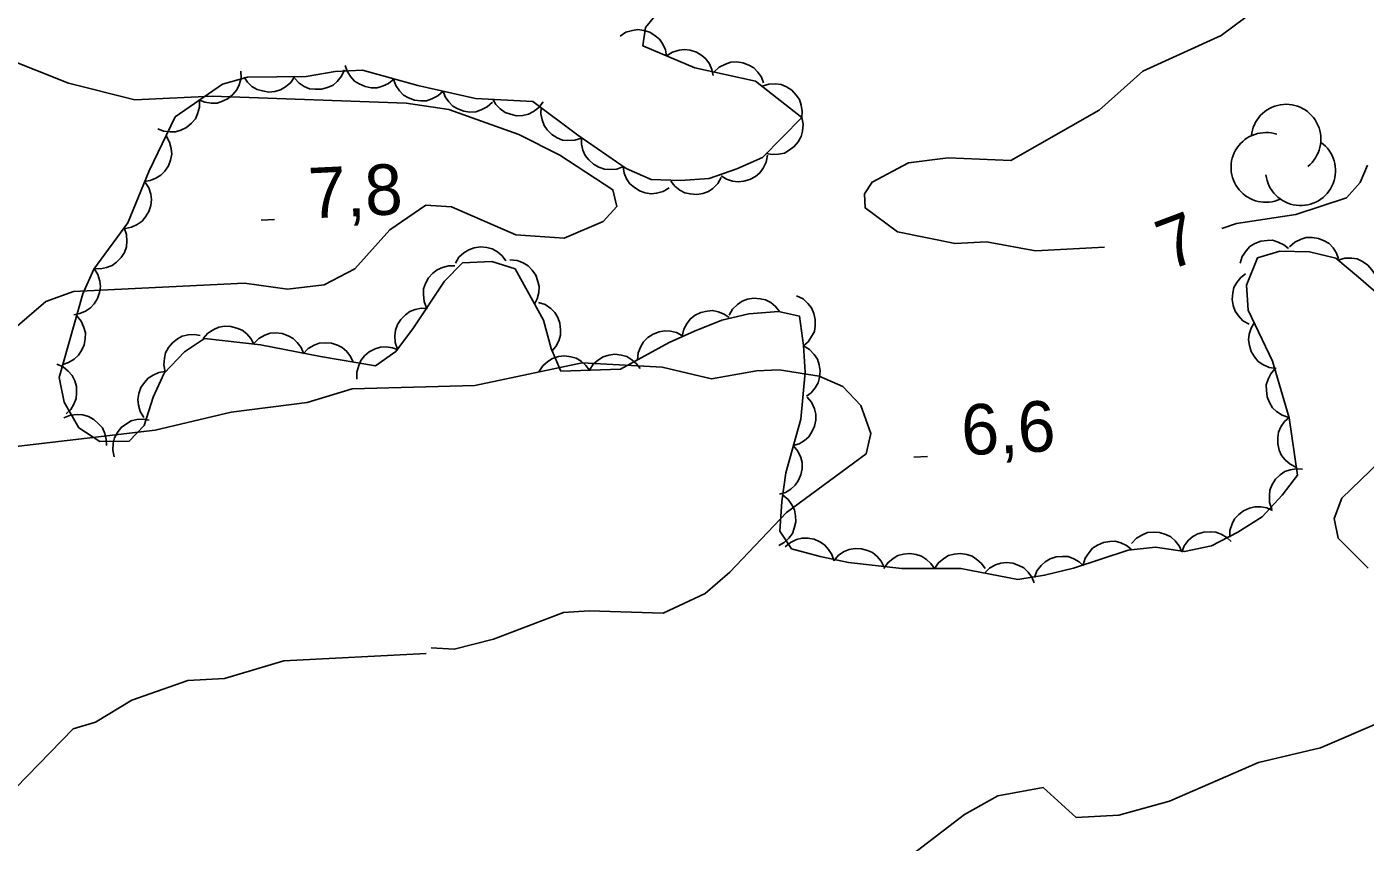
# Model space of a CAD drawing. Extents: x 336540 to 340074, y 5572036 to 5573747.
# Drawn here: x 337234.8 to 337314.2, y 5572821.1 to 5572869.5 of the extents above; entities that cross this region are included whole.
import ezdxf

# ---------------------------------------------------------------- set-up
doc = ezdxf.new("R2010")
doc.units = 0
for name, color, linetype in [('Niveau 2', 7, 'Continuous'), ('Niveau 3', 7, 'Continuous'), ('Niveau 44', 7, 'Continuous')]:
    doc.layers.add(name, color=color, linetype=linetype)

msp = doc.modelspace()

# ---------------------------------------------------------------- linework, layer by layer
at = {"layer": 'Niveau 2'}
for points in [[(337298.77, 5572856.38), (337294.68, 5572856.17), (337291.76, 5572856.69), (337289.9, 5572856.59), (337286.49, 5572857.28), (337284.56, 5572858.71), (337284.52, 5572859.55), (337284.98, 5572860.24), (337287.13, 5572861.38), (337289.49, 5572861.68), (337293.2, 5572861.53), (337298.46, 5572864.51), (337301.05, 5572866.83), (337305.69, 5572868.94), (337307.16, 5572870.03), (337310.32, 5572871.05), (337315.02, 5572871.79)], [(337229.71, 5572869.12), (337237.29, 5572866.11), (337241.23, 5572865.13), (337245.81, 5572865.35), (337257.33, 5572864.93), (337259.87, 5572864.55), (337264.02, 5572863.07), (337266.45, 5572861.84), (337269.6, 5572859.79), (337269.82, 5572858.8), (337269.02, 5572857.91), (337266.7, 5572856.92), (337263.83, 5572857.11), (337260.01, 5572858.78), (337258.49, 5572858.88), (337256.35, 5572857.41), (337254.28, 5572855.1), (337252.47, 5572854.15), (337250.28, 5572853.89), (337247.74, 5572854.25), (337237.59, 5572853.74), (337235.95, 5572853.15), (337233.82, 5572851.34)], [(337314.38, 5572861.25), (337313.93, 5572860.22), (337313.12, 5572859.31), (337310.13, 5572858.31), (337306.61, 5572857.79), (337305.73, 5572857.48)], [(337231.98, 5572844.29), (337242.43, 5572845.51), (337246.94, 5572846.58), (337251.46, 5572847.15), (337254.13, 5572847.97), (337261.4, 5572848.17), (337267.77, 5572849.52), (337272.51, 5572849.26), (337275.44, 5572848.57), (337278.12, 5572849.03), (337279.46, 5572849.09), (337281.84, 5572848.72), (337283.25, 5572848.11), (337284.3, 5572846.98), (337284.91, 5572845.32), (337284.63, 5572844.12), (337279.89, 5572840.63), (337276.53, 5572837.08), (337275.07, 5572835.82), (337272.58, 5572834.66), (337268.18, 5572834.79), (337266.66, 5572834.7), (337262.51, 5572833.12), (337260.18, 5572832.51), (337258.81, 5572832.59)], [(337315.11, 5572843.66), (337312.86, 5572841.49), (337312.4, 5572840.28), (337312.63, 5572839.11), (337314.42, 5572837.33)], [(337229.38, 5572819.38), (337237.57, 5572827.79), (337238.9, 5572828.19), (337241.04, 5572829.5), (337244.37, 5572830.66), (337246.55, 5572830.78), (337250.07, 5572831.83), (337258.51, 5572832.26)], [(337315.22, 5572828.22), (337311.58, 5572826.67), (337307.91, 5572825.8), (337302.62, 5572823.49), (337299.61, 5572822.66), (337297.08, 5572822.53), (337295.12, 5572824.3), (337292.44, 5572823.82), (337290.47, 5572822.71), (337286.4, 5572819.61)]]:
    msp.add_lwpolyline(points, dxfattribs=at)
at = {"layer": 'Niveau 3'}
for p, q in [((337248.72, 5572857.98), (337249.52, 5572858.02)), ((337287.46, 5572843.92), (337288.26, 5572843.96))]:
    msp.add_line(p, q, dxfattribs=at)
at = {"layer": 'Niveau 44'}
for points in [[(337272.63, 5572870.77), (337271.53, 5572869.42), (337271.37, 5572868.33), (337274.45, 5572867.03), (337278.06, 5572866.24), (337280.8, 5572864.08), (337278.48, 5572861.71), (337276.96, 5572861.03), (337275.3, 5572860.46), (337273.61, 5572860.33), (337271.86, 5572860.39), (337270.39, 5572861.05), (337267.51, 5572863.02), (337264.85, 5572865.03), (337261.45, 5572865.21), (337258.02, 5572865.98), (337254.74, 5572866.88), (337253.11, 5572866.81), (337251.39, 5572866.5), (337247.91, 5572866.47), (337246.42, 5572866.05), (337243.62, 5572864.11), (337242.08, 5572860.9), (337240.82, 5572857.83), (337238.8, 5572855.07), (337238.15, 5572853.6), (337236.74, 5572848.65), (337237.03, 5572847.17), (337237.91, 5572845.66), (337239.16, 5572844.85), (337240.9, 5572844.87), (337241.78, 5572845.8), (337242.32, 5572847.48), (337242.96, 5572848.9), (337244.17, 5572850.16), (337245.37, 5572850.95), (337248.69, 5572850.59), (337252.25, 5572849.88), (337255.51, 5572849.33), (337256.72, 5572850.19), (337257.76, 5572851.6), (337259.6, 5572854.36), (337260.67, 5572855.44), (337262.42, 5572855.53), (337263.79, 5572855.09), (337265.47, 5572852.05), (337265.94, 5572850.36), (337266.51, 5572849.02), (337270.05, 5572849.13), (337272.94, 5572850.73), (337274.44, 5572851.39), (337276.07, 5572852.04), (337277.67, 5572852.43), (337279.42, 5572852.57), (337280.67, 5572852.28), (337280.91, 5572850.55), (337281, 5572848.96), (337280.75, 5572846.18), (337279.85, 5572842.98), (337279.63, 5572841.28), (337279.51, 5572839.53), (337280.2, 5572838.48), (337281.89, 5572838.01), (337283.57, 5572837.67), (337286.74, 5572837.3), (337290.25, 5572837.3), (337293.63, 5572836.65), (337295.21, 5572836.91), (337296.92, 5572837.32), (337300.17, 5572838.39)], [(337270.02, 5572868.9), (337270.37, 5572869.13), (337270.76, 5572869.24), (337271.08, 5572869.29), (337271.43, 5572869.24), (337271.78, 5572869.13), (337272.11, 5572868.92), (337272.36, 5572868.72), (337272.56, 5572868.43), (337272.71, 5572868.09), (337272.78, 5572867.74)], [(337272.78, 5572867.74), (337273.13, 5572867.96), (337273.52, 5572868.08), (337273.85, 5572868.12), (337274.19, 5572868.08), (337274.55, 5572867.96), (337274.87, 5572867.76), (337275.12, 5572867.55), (337275.32, 5572867.26), (337275.47, 5572866.92), (337275.54, 5572866.57)], [(337256.61, 5572866.37), (337256.29, 5572866.1), (337255.92, 5572865.93), (337255.6, 5572865.84), (337255.25, 5572865.84), (337254.89, 5572865.91), (337254.54, 5572866.07), (337254.26, 5572866.24), (337254.03, 5572866.51), (337253.83, 5572866.82), (337253.71, 5572867.16)], [(337275.61, 5572866.78), (337275.91, 5572867.06), (337276.28, 5572867.25), (337276.59, 5572867.35), (337276.94, 5572867.37), (337277.31, 5572867.32), (337277.66, 5572867.18), (337277.95, 5572867.03), (337278.19, 5572866.77), (337278.41, 5572866.47), (337278.54, 5572866.14)], [(337247.52, 5572866.82), (337247.53, 5572866.4), (337247.42, 5572866.01), (337247.28, 5572865.71), (337247.05, 5572865.44), (337246.77, 5572865.2), (337246.42, 5572865.04), (337246.11, 5572864.93), (337245.76, 5572864.92), (337245.39, 5572864.98), (337245.06, 5572865.11)], [(337250.71, 5572866.49), (337250.48, 5572866.15), (337250.16, 5572865.89), (337249.88, 5572865.71), (337249.54, 5572865.62), (337249.17, 5572865.58), (337248.8, 5572865.65), (337248.48, 5572865.73), (337248.18, 5572865.92), (337247.91, 5572866.17), (337247.71, 5572866.47)], [(337253.67, 5572866.91), (337253.5, 5572866.53), (337253.23, 5572866.22), (337252.99, 5572866), (337252.67, 5572865.85), (337252.31, 5572865.76), (337251.93, 5572865.75), (337251.6, 5572865.78), (337251.28, 5572865.92), (337250.97, 5572866.12), (337250.72, 5572866.38)], [(337259.52, 5572865.64), (337259.21, 5572865.36), (337258.85, 5572865.18), (337258.54, 5572865.07), (337258.19, 5572865.06), (337257.82, 5572865.11), (337257.46, 5572865.25), (337257.18, 5572865.41), (337256.93, 5572865.66), (337256.72, 5572865.97), (337256.59, 5572866.3)], [(337262.45, 5572864.99), (337262.14, 5572864.7), (337261.78, 5572864.52), (337261.46, 5572864.41), (337261.11, 5572864.4), (337260.75, 5572864.45), (337260.39, 5572864.59), (337260.1, 5572864.75), (337259.86, 5572865), (337259.65, 5572865.31), (337259.52, 5572865.64)], [(337278.45, 5572865.94), (337278.84, 5572866.06), (337279.25, 5572866.07), (337279.58, 5572866.03), (337279.9, 5572865.89), (337280.21, 5572865.69), (337280.47, 5572865.4), (337280.66, 5572865.14), (337280.77, 5572864.8), (337280.83, 5572864.44), (337280.8, 5572864.08)], [(337245.06, 5572865.11), (337245.06, 5572864.69), (337244.95, 5572864.3), (337244.82, 5572864), (337244.59, 5572863.73), (337244.3, 5572863.49), (337243.96, 5572863.33), (337243.65, 5572863.22), (337243.3, 5572863.22), (337242.93, 5572863.27), (337242.59, 5572863.4)], [(337265.46, 5572865), (337265.21, 5572864.66), (337264.88, 5572864.43), (337264.59, 5572864.27), (337264.25, 5572864.2), (337263.88, 5572864.18), (337263.51, 5572864.27), (337263.2, 5572864.37), (337262.91, 5572864.58), (337262.65, 5572864.85), (337262.47, 5572865.16)], [(337267.73, 5572862.85), (337267.34, 5572862.72), (337266.93, 5572862.7), (337266.6, 5572862.73), (337266.28, 5572862.87), (337265.97, 5572863.06), (337265.7, 5572863.34), (337265.51, 5572863.6), (337265.39, 5572863.93), (337265.32, 5572864.3), (337265.34, 5572864.66)], [(337280.8, 5572864.08), (337280.88, 5572863.67), (337280.84, 5572863.26), (337280.77, 5572862.94), (337280.6, 5572862.64), (337280.36, 5572862.35), (337280.05, 5572862.13), (337279.77, 5572861.96), (337279.42, 5572861.89), (337279.05, 5572861.87), (337278.7, 5572861.93)], [(337243.08, 5572862.98), (337243.29, 5572862.62), (337243.38, 5572862.23), (337243.42, 5572861.9), (337243.35, 5572861.55), (337243.22, 5572861.21), (337243, 5572860.89), (337242.78, 5572860.65), (337242.48, 5572860.47), (337242.14, 5572860.33), (337241.78, 5572860.28)], [(337270.22, 5572861.17), (337269.83, 5572861.01), (337269.42, 5572860.98), (337269.09, 5572861), (337268.76, 5572861.12), (337268.44, 5572861.3), (337268.17, 5572861.56), (337267.96, 5572861.81), (337267.82, 5572862.14), (337267.74, 5572862.5), (337267.74, 5572862.86)], [(337278.77, 5572861.84), (337278.69, 5572861.43), (337278.51, 5572861.06), (337278.32, 5572860.79), (337278.05, 5572860.57), (337277.73, 5572860.39), (337277.36, 5572860.3), (337277.03, 5572860.25), (337276.69, 5572860.3), (337276.33, 5572860.42), (337276.03, 5572860.61)], [(337272.94, 5572859.91), (337272.58, 5572859.69), (337272.19, 5572859.58), (337271.86, 5572859.54), (337271.51, 5572859.6), (337271.17, 5572859.72), (337270.85, 5572859.93), (337270.6, 5572860.14), (337270.41, 5572860.44), (337270.26, 5572860.78), (337270.2, 5572861.14)], [(337241.82, 5572860.26), (337242.05, 5572859.91), (337242.17, 5572859.53), (337242.22, 5572859.2), (337242.17, 5572858.85), (337242.06, 5572858.5), (337241.86, 5572858.17), (337241.66, 5572857.92), (337241.37, 5572857.72), (337241.03, 5572857.56), (337240.68, 5572857.49)], [(337276.03, 5572860.52), (337275.83, 5572860.15), (337275.53, 5572859.87), (337275.26, 5572859.68), (337274.93, 5572859.57), (337274.57, 5572859.5), (337274.18, 5572859.54), (337273.86, 5572859.6), (337273.56, 5572859.77), (337273.27, 5572860), (337273.04, 5572860.29)], [(337240.6, 5572857.53), (337240.74, 5572857.14), (337240.76, 5572856.73), (337240.73, 5572856.4), (337240.61, 5572856.07), (337240.41, 5572855.76), (337240.14, 5572855.49), (337239.88, 5572855.29), (337239.55, 5572855.17), (337239.19, 5572855.1), (337238.83, 5572855.11)], [(337306.82, 5572855.43), (337306.94, 5572855.83), (337307.17, 5572856.17), (337307.39, 5572856.41), (337307.69, 5572856.6), (337308.04, 5572856.73), (337308.42, 5572856.78), (337308.74, 5572856.79), (337309.08, 5572856.68), (337309.41, 5572856.52), (337309.69, 5572856.29)], [(337309.75, 5572856.4), (337310.06, 5572856.68), (337310.43, 5572856.85), (337310.74, 5572856.95), (337311.1, 5572856.96), (337311.46, 5572856.9), (337311.81, 5572856.75), (337312.1, 5572856.59), (337312.33, 5572856.33), (337312.54, 5572856.02), (337312.66, 5572855.68)], [(337260.25, 5572855.42), (337260.46, 5572855.78), (337260.76, 5572856.05), (337261.04, 5572856.23), (337261.37, 5572856.34), (337261.74, 5572856.39), (337262.12, 5572856.35), (337262.44, 5572856.28), (337262.74, 5572856.1), (337263.02, 5572855.86), (337263.24, 5572855.57)], [(337300.17, 5572838.39), (337301.79, 5572838.58), (337303.52, 5572838.31), (337305.12, 5572838.65), (337306.68, 5572839.46), (337308.13, 5572840.37), (337309.32, 5572841.65), (337310.23, 5572842.84), (337309.72, 5572846.25), (337308.74, 5572849.61), (337307.29, 5572852.63), (337307.19, 5572854.12), (337307.84, 5572855.74), (337309.18, 5572856.14), (337310.93, 5572856.11), (337312.5, 5572855.72), (337313.85, 5572854.6), (337315.03, 5572853.57)], [(337258.54, 5572852.78), (337258.39, 5572853.16), (337258.35, 5572853.57), (337258.36, 5572853.9), (337258.47, 5572854.23), (337258.65, 5572854.55), (337258.92, 5572854.83), (337259.16, 5572855.04), (337259.49, 5572855.18), (337259.85, 5572855.27), (337260.21, 5572855.27)], [(337263.49, 5572855.63), (337263.91, 5572855.59), (337264.28, 5572855.44), (337264.57, 5572855.28), (337264.81, 5572855.02), (337265.02, 5572854.71), (337265.15, 5572854.35), (337265.22, 5572854.04), (337265.2, 5572853.68), (337265.11, 5572853.32), (337264.94, 5572853)], [(337312.63, 5572855.61), (337313.03, 5572855.73), (337313.44, 5572855.73), (337313.76, 5572855.68), (337314.08, 5572855.53), (337314.39, 5572855.32), (337314.64, 5572855.03), (337314.82, 5572854.76), (337314.92, 5572854.42), (337314.97, 5572854.06), (337314.94, 5572853.7)], [(337238.82, 5572855.12), (337239.04, 5572854.76), (337239.15, 5572854.37), (337239.19, 5572854.04), (337239.14, 5572853.69), (337239.02, 5572853.34), (337238.81, 5572853.02), (337238.6, 5572852.77), (337238.3, 5572852.58), (337237.96, 5572852.44), (337237.61, 5572852.37)], [(337307.35, 5572851.8), (337306.98, 5572852.01), (337306.71, 5572852.31), (337306.52, 5572852.58), (337306.4, 5572852.92), (337306.35, 5572853.28), (337306.39, 5572853.66), (337306.45, 5572853.98), (337306.63, 5572854.29), (337306.86, 5572854.58), (337307.14, 5572854.8)], [(337256.82, 5572850.32), (337256.68, 5572850.72), (337256.66, 5572851.12), (337256.69, 5572851.45), (337256.82, 5572851.78), (337257.01, 5572852.09), (337257.29, 5572852.36), (337257.54, 5572852.56), (337257.87, 5572852.68), (337258.24, 5572852.75), (337258.6, 5572852.74)], [(337265.18, 5572853.1), (337265.57, 5572852.97), (337265.91, 5572852.73), (337266.15, 5572852.51), (337266.32, 5572852.2), (337266.45, 5572851.86), (337266.49, 5572851.47), (337266.49, 5572851.15), (337266.38, 5572850.81), (337266.21, 5572850.48), (337265.98, 5572850.21)], [(337276.49, 5572852.34), (337276.69, 5572852.7), (337276.99, 5572852.98), (337277.26, 5572853.17), (337277.59, 5572853.29), (337277.95, 5572853.35), (337278.33, 5572853.32), (337278.65, 5572853.26), (337278.96, 5572853.09), (337279.25, 5572852.86), (337279.48, 5572852.57)], [(337280.5, 5572853.49), (337280.88, 5572853.31), (337281.17, 5572853.03), (337281.38, 5572852.77), (337281.52, 5572852.45), (337281.6, 5572852.09), (337281.59, 5572851.71), (337281.55, 5572851.38), (337281.39, 5572851.07), (337281.18, 5572850.76), (337280.91, 5572850.52)], [(337237.78, 5572852.31), (337238.05, 5572851.99), (337238.21, 5572851.61), (337238.3, 5572851.3), (337238.29, 5572850.94), (337238.22, 5572850.58), (337238.06, 5572850.24), (337237.89, 5572849.96), (337237.62, 5572849.73), (337237.3, 5572849.54), (337236.96, 5572849.42)], [(337273.71, 5572851.1), (337273.8, 5572851.51), (337274, 5572851.86), (337274.2, 5572852.13), (337274.48, 5572852.34), (337274.81, 5572852.5), (337275.19, 5572852.58), (337275.51, 5572852.62), (337275.85, 5572852.55), (337276.2, 5572852.41), (337276.5, 5572852.21)], [(337243.03, 5572848.98), (337242.95, 5572849.39), (337242.98, 5572849.79), (337243.05, 5572850.11), (337243.22, 5572850.42), (337243.46, 5572850.71), (337243.76, 5572850.94), (337244.04, 5572851.1), (337244.39, 5572851.18), (337244.76, 5572851.2), (337245.11, 5572851.14)], [(337245.29, 5572850.96), (337245.56, 5572851.28), (337245.91, 5572851.5), (337246.21, 5572851.64), (337246.55, 5572851.69), (337246.92, 5572851.68), (337247.29, 5572851.58), (337247.59, 5572851.46), (337247.87, 5572851.23), (337248.11, 5572850.95), (337248.28, 5572850.63)], [(337248.28, 5572850.67), (337248.58, 5572850.96), (337248.94, 5572851.15), (337249.25, 5572851.27), (337249.6, 5572851.29), (337249.97, 5572851.25), (337250.33, 5572851.11), (337250.62, 5572850.96), (337250.87, 5572850.72), (337251.09, 5572850.42), (337251.23, 5572850.08)], [(337271.06, 5572849.69), (337271.1, 5572850.11), (337271.25, 5572850.48), (337271.42, 5572850.77), (337271.67, 5572851.01), (337271.98, 5572851.22), (337272.34, 5572851.35), (337272.66, 5572851.42), (337273.01, 5572851.4), (337273.37, 5572851.31), (337273.69, 5572851.14)], [(337308.95, 5572849.18), (337308.53, 5572849.24), (337308.17, 5572849.41), (337307.89, 5572849.59), (337307.66, 5572849.86), (337307.47, 5572850.18), (337307.37, 5572850.55), (337307.31, 5572850.87), (337307.36, 5572851.22), (337307.47, 5572851.57), (337307.65, 5572851.88)], [(337251.22, 5572850.05), (337251.51, 5572850.36), (337251.86, 5572850.56), (337252.17, 5572850.68), (337252.52, 5572850.71), (337252.89, 5572850.68), (337253.25, 5572850.56), (337253.54, 5572850.42), (337253.8, 5572850.18), (337254.03, 5572849.88), (337254.18, 5572849.55)], [(337254.41, 5572848.55), (337254.4, 5572848.96), (337254.51, 5572849.36), (337254.64, 5572849.66), (337254.86, 5572849.93), (337255.14, 5572850.17), (337255.49, 5572850.34), (337255.8, 5572850.45), (337256.15, 5572850.46), (337256.52, 5572850.41), (337256.85, 5572850.29)], [(337280.91, 5572850.52), (337281.27, 5572850.31), (337281.54, 5572850.01), (337281.73, 5572849.73), (337281.84, 5572849.4), (337281.89, 5572849.03), (337281.85, 5572848.65), (337281.78, 5572848.33), (337281.6, 5572848.03), (337281.37, 5572847.74), (337281.08, 5572847.53)], [(337265.21, 5572848.98), (337265.43, 5572849.33), (337265.74, 5572849.6), (337266.02, 5572849.78), (337266.36, 5572849.88), (337266.72, 5572849.92), (337267.1, 5572849.87), (337267.42, 5572849.79), (337267.72, 5572849.61), (337268, 5572849.36), (337268.21, 5572849.07)], [(337268.21, 5572849.07), (337268.43, 5572849.43), (337268.74, 5572849.69), (337269.02, 5572849.87), (337269.35, 5572849.97), (337269.72, 5572850.02), (337270.1, 5572849.96), (337270.42, 5572849.89), (337270.72, 5572849.7), (337271, 5572849.46), (337271.21, 5572849.17)], [(337236.59, 5572849.44), (337236.97, 5572849.28), (337237.28, 5572849.01), (337237.5, 5572848.77), (337237.66, 5572848.45), (337237.76, 5572848.1), (337237.77, 5572847.72), (337237.74, 5572847.39), (337237.61, 5572847.07), (337237.42, 5572846.75), (337237.16, 5572846.49)], [(337241.77, 5572846.26), (337241.55, 5572846.62), (337241.45, 5572847.01), (337241.41, 5572847.34), (337241.47, 5572847.69), (337241.59, 5572848.04), (337241.8, 5572848.35), (337242.01, 5572848.6), (337242.31, 5572848.79), (337242.65, 5572848.94), (337243, 5572849)], [(337309.71, 5572846.27), (337309.32, 5572846.4), (337308.98, 5572846.63), (337308.74, 5572846.85), (337308.56, 5572847.15), (337308.42, 5572847.5), (337308.38, 5572847.88), (337308.37, 5572848.21), (337308.48, 5572848.54), (337308.64, 5572848.87), (337308.87, 5572849.15)], [(337281.12, 5572847.48), (337281.39, 5572847.17), (337281.55, 5572846.79), (337281.64, 5572846.47), (337281.63, 5572846.12), (337281.56, 5572845.76), (337281.4, 5572845.41), (337281.23, 5572845.13), (337280.96, 5572844.9), (337280.65, 5572844.71), (337280.3, 5572844.6)], [(337237.02, 5572846.24), (337237.41, 5572846.4), (337237.81, 5572846.44), (337238.14, 5572846.43), (337238.47, 5572846.32), (337238.8, 5572846.15), (337239.08, 5572845.89), (337239.3, 5572845.65), (337239.44, 5572845.32), (337239.53, 5572844.96), (337239.54, 5572844.6)], [(337240.01, 5572843.93), (337239.92, 5572844.34), (337239.95, 5572844.75), (337240.02, 5572845.07), (337240.19, 5572845.38), (337240.42, 5572845.67), (337240.73, 5572845.9), (337241.01, 5572846.07), (337241.35, 5572846.15), (337241.72, 5572846.17), (337242.08, 5572846.11)], [(337310.16, 5572843.31), (337309.78, 5572843.49), (337309.48, 5572843.76), (337309.27, 5572844.01), (337309.13, 5572844.34), (337309.05, 5572844.7), (337309.05, 5572845.08), (337309.09, 5572845.4), (337309.24, 5572845.72), (337309.45, 5572846.03), (337309.72, 5572846.27)], [(337280.3, 5572844.6), (337280.57, 5572844.28), (337280.74, 5572843.9), (337280.82, 5572843.59), (337280.82, 5572843.23), (337280.75, 5572842.87), (337280.59, 5572842.52), (337280.42, 5572842.25), (337280.15, 5572842.02), (337279.83, 5572841.82), (337279.49, 5572841.71)], [(337308.69, 5572840.83), (337308.56, 5572841.23), (337308.55, 5572841.63), (337308.58, 5572841.96), (337308.72, 5572842.29), (337308.92, 5572842.6), (337309.2, 5572842.86), (337309.46, 5572843.06), (337309.79, 5572843.17), (337310.16, 5572843.23), (337310.52, 5572843.21)], [(337279.66, 5572841.67), (337279.99, 5572841.41), (337280.22, 5572841.08), (337280.37, 5572840.79), (337280.44, 5572840.44), (337280.45, 5572840.07), (337280.36, 5572839.7), (337280.25, 5572839.39), (337280.03, 5572839.11), (337279.76, 5572838.86), (337279.45, 5572838.68)], [(337306.2, 5572839.16), (337306.21, 5572839.57), (337306.34, 5572839.96), (337306.49, 5572840.25), (337306.73, 5572840.51), (337307.02, 5572840.73), (337307.38, 5572840.88), (337307.69, 5572840.97), (337308.04, 5572840.96), (337308.41, 5572840.9), (337308.74, 5572840.75)], [(337300.38, 5572838.8), (337300.66, 5572839.11), (337301.02, 5572839.31), (337301.32, 5572839.44), (337301.67, 5572839.47), (337302.04, 5572839.45), (337302.4, 5572839.33), (337302.7, 5572839.19), (337302.96, 5572838.95), (337303.19, 5572838.66), (337303.34, 5572838.34)], [(337303.35, 5572838.27), (337303.5, 5572838.66), (337303.76, 5572838.98), (337304, 5572839.2), (337304.31, 5572839.36), (337304.67, 5572839.47), (337305.05, 5572839.49), (337305.37, 5572839.46), (337305.7, 5572839.34), (337306.02, 5572839.15), (337306.28, 5572838.9)], [(337279.81, 5572838.59), (337280.13, 5572838.86), (337280.5, 5572839.02), (337280.82, 5572839.11), (337281.17, 5572839.11), (337281.54, 5572839.04), (337281.88, 5572838.88), (337282.16, 5572838.71), (337282.39, 5572838.44), (337282.59, 5572838.13), (337282.7, 5572837.78)], [(337282.7, 5572837.77), (337282.98, 5572838.09), (337283.32, 5572838.31), (337283.62, 5572838.44), (337283.97, 5572838.49), (337284.34, 5572838.48), (337284.71, 5572838.38), (337285.01, 5572838.25), (337285.28, 5572838.02), (337285.52, 5572837.74), (337285.68, 5572837.42)], [(337297.51, 5572837.52), (337297.63, 5572837.92), (337297.85, 5572838.26), (337298.06, 5572838.51), (337298.36, 5572838.7), (337298.7, 5572838.85), (337299.08, 5572838.91), (337299.4, 5572838.92), (337299.74, 5572838.83), (337300.08, 5572838.67), (337300.36, 5572838.45)], [(337285.68, 5572837.3), (337285.91, 5572837.65), (337286.23, 5572837.9), (337286.51, 5572838.07), (337286.85, 5572838.16), (337287.22, 5572838.2), (337287.59, 5572838.13), (337287.91, 5572838.04), (337288.2, 5572837.85), (337288.47, 5572837.6), (337288.68, 5572837.3)], [(337288.68, 5572837.3), (337288.91, 5572837.65), (337289.23, 5572837.9), (337289.51, 5572838.07), (337289.85, 5572838.16), (337290.22, 5572838.2), (337290.59, 5572838.13), (337290.91, 5572838.04), (337291.2, 5572837.85), (337291.47, 5572837.6), (337291.68, 5572837.3)], [(337291.65, 5572837.03), (337291.95, 5572837.33), (337292.3, 5572837.52), (337292.61, 5572837.63), (337292.97, 5572837.66), (337293.33, 5572837.62), (337293.69, 5572837.49), (337293.98, 5572837.34), (337294.24, 5572837.09), (337294.46, 5572836.79), (337294.6, 5572836.46)], [(337294.61, 5572836.77), (337294.76, 5572837.16), (337295.01, 5572837.48), (337295.24, 5572837.71), (337295.55, 5572837.88), (337295.9, 5572838), (337296.28, 5572838.02), (337296.61, 5572838.01), (337296.94, 5572837.89), (337297.26, 5572837.71), (337297.53, 5572837.47)]]:
    msp.add_lwpolyline(points, dxfattribs=at)
for centre, start, end in [((337309.542, 5572862.787), 308.75063, 174.43922), ((337308.346, 5572861.112), 71.57212, 294.25648), ((337310.406, 5572860.918), 186.90443, 54.36151)]:
    msp.add_arc(centre, 2.07, start, end, dxfattribs=at)

# ---------------------------------------------------------------- texts
at = {"layer": 'Niveau 2'}
msp.add_text('7', height=3, rotation=20.50799, dxfattribs=at).set_placement((337302.58, 5572854.97))
at = {"layer": 'Niveau 3'}
for s, p in [('7,8    ', (337251.6, 5572858.08)), ('6,6    ', (337290.34, 5572844.02))]:
    msp.add_text(s, height=3, rotation=2.7712, dxfattribs=at).set_placement(p)

doc.saveas('drawing.dxf')
